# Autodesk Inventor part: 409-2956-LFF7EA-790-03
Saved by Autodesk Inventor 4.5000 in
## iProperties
Created: 2010-09
Part Number: 409-2956-LFF7EA-790-03
Cost Center: 0 lbmass
Material: A36 STEEL PLATE
Document SubType Name: Sheet Metal
Designer: S. Boerckel
Authority: 0 in^3
Mass: 2019.1 g
Surface Area: 484.956 cm^2
Volume: 256.883 cm^3
Density: 7.86 g/cm^3
Flat Pattern Width: 11.43 cm
Flat Pattern Length: 17.78 cm
Flat Pattern Area: 203.225 cm^2
Sheet Metal Rule: 1/2"Thk
Sheet Metal Width: 7.0000 in
Sheet Metal Length: 31.5000 in^2
Description: WELD PLATE
User Status: MACHINE
SaveDate: 2008-01-15
SaveTime: 10:24
FileName: Sheet Metal
Wide: =<Flat Pattern Width>cm
Length: =<Flat Pattern Length>cm
Thickness: 0.5000 in
SMR: =<Sheet Metal Rule> - <Material>
Author: S. Boerckel
Revision Number: 0
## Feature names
1. Hole1
2. Plate1
